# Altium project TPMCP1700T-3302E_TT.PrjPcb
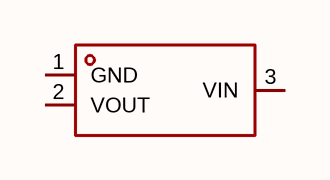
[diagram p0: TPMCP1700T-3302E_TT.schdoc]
1 sheet, 1 parts. Net scope: global (net labels, ports and power ports of the same name join across sheets).

## Sheet TPMCP1700T-3302E_TT.schdoc
size 127 x 101 mm

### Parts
U?  tpmcp1700t-3302e/tt  [SOT-23-3_L2.9-W1.6-P1.90-LS2.8-BR]  (value not drawn)

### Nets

Not connected (* = marked no-connect by the designer): U? 1(GND) 2(VOUT) 3(VIN)

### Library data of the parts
U? = tpmcp1700t-3302e/tt: 输出极性:正极;工作电压:6.5V;输出电压:3.3V;输出电流:450mA;电源纹波抑制比(PSRR):40dB@(1kHz);输出类型:固定;; Manufacturer: TECH PUBLIC(台舟); AddInBom: yes; ModelId: 89cb27a44ab2466697082bb9fd73a7d0; ModelName: SOT-23-3L_L2.9-W1.6-H1.1-LS2.8-P0.95; ModelTransform: 114.173,110.236,0,90,0,0,0,0,0; Output Configuration: 正极; Voltage - Supply: 6.5V; Output Voltage: 3.3V; Output Current: 450mA; Voltage Dropout: 170mV@(250mA); standby current: 1.6uA; Output Type: 固定; Number of Outputs: 1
